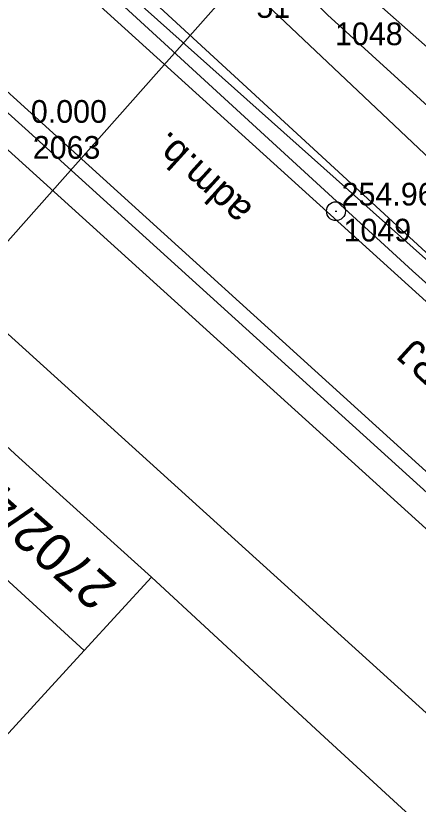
# Model space of a CAD drawing. Extents: x -496688 to -495455, y -1089309 to -1088026.
# Drawn here: x -496224.8 to -496203.55, y -1088502.54 to -1088460.89 of the extents above; entities that cross this region are included whole.
import ezdxf

# ---------------------------------------------------------------- set-up
doc = ezdxf.new("R2010")
doc.units = 0
for name, color, linetype in [('Vrstva 1', 7, 'Continuous'), ('Vrstva 16', 7, 'Continuous'), ('Vrstva 23', 7, 'Continuous'), ('Vrstva 25', 7, 'Continuous'), ('Vrstva 36', 7, 'Continuous'), ('Vrstva 51', 7, 'Continuous'), ('Vrstva 53', 7, 'Continuous'), ('Vrstva 55', 7, 'Continuous'), ('Vrstva 57', 7, 'Continuous'), ('Vrstva 6', 7, 'Continuous'), ('Vrstva 60', 7, 'Continuous'), ('Vrstva 61', 7, 'Continuous')]:
    doc.layers.add(name, color=color, linetype=linetype)

msp = doc.modelspace()

# ---------------------------------------------------------------- linework, layer by layer
at = {"layer": 'Vrstva 1'}
for points in [[(-496187.893, -1088475.966), (-496191.868, -1088472.437), (-496209.635, -1088456.735), (-496220.575, -1088447.084)], [(-496222.025, -1088448.74), (-496212.497, -1088459.397), (-496194.892, -1088476.055)]]:
    msp.add_lwpolyline(points, dxfattribs=at)
at = {"layer": 'Vrstva 16'}
msp.add_lwpolyline([(-496184.629, -1088475.67), (-496187.454, -1088475.604), (-496194.899, -1088468.574), (-496191.403, -1088465.223), (-496199.911, -1088458.038), (-496208.371, -1088451.846), (-496216.95, -1088446.6), (-496219.092, -1088449.299), (-496214.995, -1088454.026), (-496208.343, -1088460.841), (-496177.898, -1088488.575), (-496173.306, -1088483.846), (-496178.781, -1088476.82)], dxfattribs=at)
at = {"layer": 'Vrstva 23'}
for p, q in [((-496224.63, -1088484.22), (-496243.12, -1088467.31)), ((-496217.64, -1088490.55), (-496224.63, -1088484.22)), ((-496228.16, -1088488.03), (-496221.19, -1088494.41)), ((-496221.19, -1088494.41), (-496217.64, -1088490.55)), ((-496208.5, -1088499), (-496217.64, -1088490.55)), ((-496221.19, -1088494.41), (-496230.49, -1088504.55)), ((-496190.39, -1088515.55), (-496208.5, -1088499))]:
    msp.add_line(p, q, dxfattribs=at)
msp.add_lwpolyline([(-496181.425, -1088495.664), (-496185.899, -1088500.598), (-496230.62, -1088460.017), (-496226.16, -1088455.098), (-496181.425, -1088495.664)], dxfattribs=at)
at = {"layer": 'Vrstva 25'}
msp.add_line((-496207.944, -1088471.21), (-496207.844, -1088471.21), dxfattribs=at)
msp.add_circle((-496207.894, -1088471.21), 0.5, dxfattribs=at)
at = {"layer": 'Vrstva 36'}
msp.add_lwpolyline([(-496223.499, -1088456.98), (-496222.478, -1088455.575), (-496197.873, -1088478.241)], dxfattribs=at)
at = {"layer": 'Vrstva 51'}
msp.add_lwpolyline([(-496180.44, -1088495.367), (-496203.858, -1088474.361), (-496223.072, -1088456.725), (-496222.68, -1088456.29), (-496203.164, -1088473.734), (-496178.299, -1088495.921), (-496180.194, -1088498.089), (-496180.951, -1088498.955)], dxfattribs=at)
at = {"layer": 'Vrstva 53'}
msp.add_lwpolyline([(-496006.16, -1088672.1), (-496009.66, -1088673.61), (-496019.34, -1088652.65), (-496125.77, -1088556.38), (-496187.85, -1088499.89), (-496224.3, -1088466.84), (-496274.7, -1088421.37), (-496308.3, -1088391.23), (-496341.24, -1088361.35), (-496344.49, -1088357.55), (-496352.49, -1088347.86), (-496352.14, -1088346.56), (-496371.02, -1088328.7), (-496406.7, -1088297.06), (-496406.34, -1088296.61), (-496407.86, -1088294.92), (-496408.29, -1088292.38), (-496407.56, -1088290.4), (-496405.24, -1088287.91)], dxfattribs=at)
at = {"layer": 'Vrstva 55'}
for p, q in [((-496235.31, -1088458.83), (-496126.78, -1088557.15)), ((-496132.08, -1088562.07), (-496238.15, -1088465.99))]:
    msp.add_line(p, q, dxfattribs=at)
at = {"layer": 'Vrstva 6'}
msp.add_line((-496238.411, -1088487.695), (-496197.033, -1088440.957), dxfattribs=at)
at = {"layer": 'Vrstva 60'}
for p, q in [((-496224.3, -1088466.84), (-496224.3, -1088466.84)), ((-496224.3, -1088466.84), (-496224.3, -1088466.84)), ((-496207.894, -1088471.21), (-496207.894, -1088471.21)), ((-496207.894, -1088471.21), (-496207.894, -1088471.21)), ((-496203.858, -1088474.361), (-496203.858, -1088474.361)), ((-496203.858, -1088474.361), (-496203.858, -1088474.361))]:
    msp.add_line(p, q, dxfattribs=at)

# ---------------------------------------------------------------- texts
at = {"layer": 'Vrstva 23'}
for s, p in [('adm.b.', (-496212.232, -1088471.012)), ('DKV,PJ', (-496198.576, -1088482.54))]:
    msp.add_text(s, height=1.5, rotation=137.7786, dxfattribs=at).set_placement(p)
at = {"layer": 'Vrstva 57'}
msp.add_text('2702/413', height=2, rotation=138.4632, dxfattribs=at).set_placement((-496219.367, -1088490.94))
at = {"layer": 'Vrstva 60'}
for s, p in [('51', (-496212.097, -1088460.997)), ('51', (-496212.097, -1088460.997)), ('1048', (-496207.943, -1088462.441)), ('1048', (-496207.943, -1088462.441)), ('2063', (-496223.9, -1088468.44)), ('2063', (-496223.9, -1088468.44)), ('1049', (-496207.494, -1088472.81)), ('1049', (-496207.494, -1088472.81))]:
    msp.add_text(s, height=1.2, dxfattribs=at).set_placement(p)
at = {"layer": 'Vrstva 61'}
for s, p in [('0.000', (-496224, -1088466.54)), ('0.000', (-496224, -1088466.54)), ('254.969', (-496207.594, -1088470.91)), ('254.969', (-496207.594, -1088470.91))]:
    msp.add_text(s, height=1.2, dxfattribs=at).set_placement(p)

doc.saveas('drawing.dxf')
